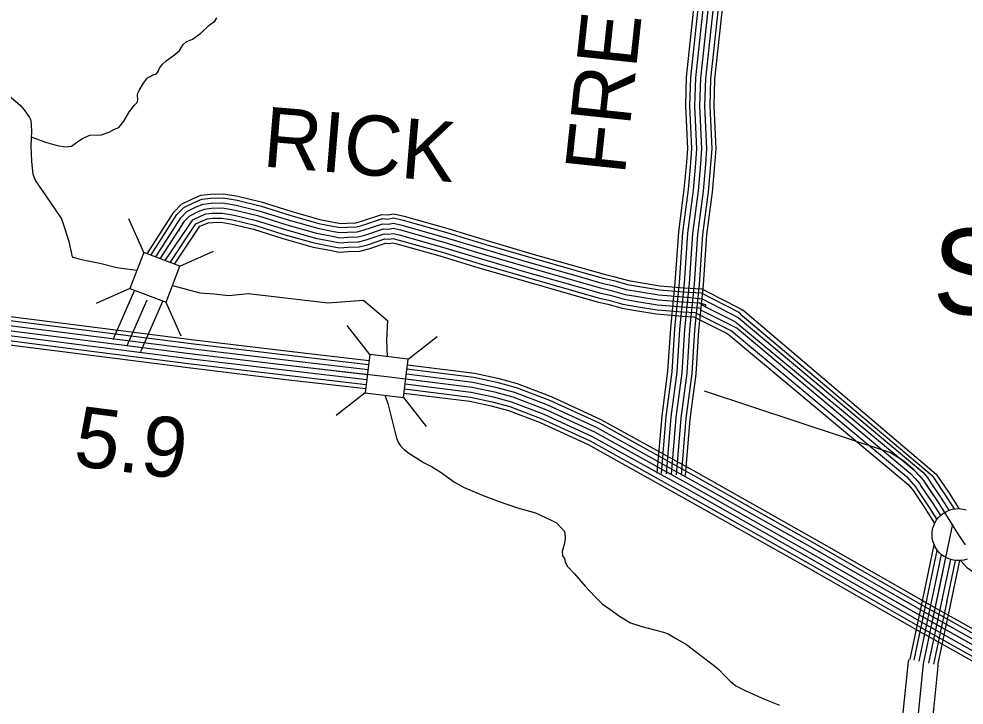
# Model space of a CAD drawing. Extents: x 1551132 to 1791609, y 378168 to 563823.
# Drawn here: x 1690071 to 1695891, y 434888 to 439114 of the extents above; entities that cross this region are included whole.
import ezdxf

# ---------------------------------------------------------------- set-up
doc = ezdxf.new("R2010")
doc.units = 0
for name, color, linetype in [('DESIGN - ROW - Right-of-Way and Easement Labels', 7, 'Continuous'), ('DESIGN - TRAFFIC CONTROL PERMANENT - Signalization', 7, 'Continuous'), ('DESIGN - TRANSPORTATION - Text', 7, 'Continuous'), ('SURVEY - CENTERLINE - Preliminary Text', 7, 'Continuous'), ('SURVEY - CONTOURS - Index with Text', 7, 'Continuous'), ('SURVEY - DRAINAGE - Storm Sewer', 7, 'Continuous'), ('SURVEY - PROPERTY - Owners', 7, 'Continuous'), ('SURVEY - TRANSPORTATION - Roads', 7, 'Continuous'), ('SURVEY - VEGETATION - Features with Text', 7, 'Continuous')]:
    doc.layers.add(name, color=color, linetype=linetype)

msp = doc.modelspace()

# ---------------------------------------------------------------- linework, layer by layer
at = {"layer": 'DESIGN - TRANSPORTATION - Text'}
for points in [[(1690147.225, 438387.515), (1690234.439, 438354.214), (1690306.237, 438335.339), (1690358.145, 438326.714), (1690394.185, 438330.297), (1690440.568, 438363.781), (1690462.725, 438377.532), (1690488.858, 438389.24), (1690506.941, 438397.032), (1690578.989, 438400.182), (1690627.163, 438415.633), (1690659.388, 438435.267), (1690685.495, 438444.975), (1690717.945, 438484.635), (1690752.61, 438544.286), (1690783.035, 438581.97), (1690799.234, 438599.796), (1690803.393, 438613.763), (1690801.743, 438645.822), (1690803.859, 438655.806), (1690812.059, 438673.731), (1690838.55, 438717.466), (1690862.925, 438751.217), (1690879.016, 438759.033), (1690895.124, 438768.85), (1690917.215, 438776.601), (1690927.365, 438790.493), (1690937.59, 438810.401), (1690955.881, 438836.21), (1690978.105, 438855.969), (1691028.521, 438893.412), (1691058.812, 438919.088), (1691083.236, 438956.839), (1691101.411, 438972.639), (1691139.61, 438990.206), (1691192.017, 439025.624), (1691242.566, 439075.084), (1691276.857, 439100.709), (1691289.081, 439120.585)], [(1689997.712, 438651.355), (1690078.951, 438582.32), (1690102.642, 438554.003), (1690122.35, 438527.744), (1690136.133, 438507.552), (1690143.933, 438489.443), (1690149.216, 438425.308), (1690144.15, 438329.255), (1690149.099, 438235.094), (1690156.233, 438156.917), (1690173.79, 438116.666), (1690215.139, 438058.106), (1690293.854, 437941.045), (1690333.203, 437882.51), (1690354.511, 437820.184), (1690377.669, 437743.823), (1690398.618, 437649.471), (1690439.376, 437636.221), (1690476.35, 437628.829), (1690569.314, 437608.745), (1690673.903, 437582.319), (1690798.026, 437566.919)], [(1691016.354, 437472.733), (1691185.2, 437426.949), (1691271.823, 437421.665), (1691362.679, 437410.04), (1691483.118, 437422.715), (1691747.22, 437391.015), (1691973.29, 437365.647), (1692193.026, 437382.556), (1692340.923, 437255.72), (1692334.464, 437134.617), (1692339.314, 437033.256)], [(1692323.889, 436795.349), (1692325.314, 436791.658), (1692342.797, 436745.39), (1692375.33, 436612.861), (1692396.438, 436532.518), (1692408.104, 436502.342), (1692419.904, 436484.183), (1692443.661, 436461.874), (1692471.419, 436439.523), (1692566.767, 436380.322), (1692610.524, 436357.78), (1692664.165, 436325.104), (1692753.454, 436259.977), (1692813.094, 436227.226), (1692928.558, 436177.809), (1693028.181, 436142.583), (1693141.753, 436103.19), (1693251.417, 436071.856), (1693348.932, 436026.646), (1693380.756, 436010.254), (1693408.439, 435981.895), (1693424.263, 435965.687)], [(1693424.263, 435965.687), (1693432.105, 435951.578), (1693433.663, 435911.518), (1693429.28, 435877.526), (1693416.797, 435833.625), (1693418.505, 435807.574), (1693430.321, 435791.415), (1693434.055, 435767.348), (1693447.771, 435741.156), (1693491.278, 435696.588), (1693558.435, 435619.703), (1693619.717, 435554.901), (1693665.207, 435508.308), (1693708.873, 435477.757), (1693768.405, 435435.006), (1693835.953, 435394.155), (1693905.71, 435371.305), (1693993.466, 435348.237), (1694039.357, 435337.679), (1694069.239, 435327.32), (1694120.905, 435296.669), (1694182.503, 435259.893), (1694269.768, 435192.783), (1694345.141, 435135.832), (1694382.807, 435105.348), (1694412.431, 435070.955), (1694452.005, 435032.446), (1694485.721, 435006.012), (1694543.403, 434977.294), (1694660.825, 434923.843), (1694754.423, 434886.692)]]:
    msp.add_lwpolyline(points, dxfattribs=at)
at = {"layer": 'SURVEY - CENTERLINE - Preliminary Text'}
for points in [[(1681622.025, 439012.586), (1682099.83, 438872.182), (1683124.214, 438579.092), (1684451.083, 438193.607), (1685427.977, 437892.65), (1685684.321, 437815.24), (1685789.718, 437786.239), (1686023.229, 437753.505), (1686441.986, 437702.812), (1687049.722, 437632.735), (1687947.351, 437524.691), (1688790.781, 437427.056), (1689660.927, 437327.162), (1690457.1, 437225.726), (1691150.425, 437137.108), (1691735.637, 437067.231), (1692227.308, 437010.672)], [(1681606.675, 438959.026), (1682084.314, 438818.672), (1683108.781, 438525.549), (1684435.117, 438140.231), (1685411.719, 437839.357), (1685668.871, 437761.697), (1685778.418, 437731.562), (1686016.013, 437698.253), (1686435.453, 437647.477), (1687043.197, 437577.392), (1687940.818, 437469.357), (1688784.398, 437371.704), (1689654.227, 437271.844), (1690450.05, 437170.458), (1691143.592, 437081.806), (1691729.153, 437011.896), (1692220.509, 436955.37)], [(1681615.192, 438988.835), (1682092.947, 438848.448), (1683117.364, 438555.341), (1684444, 438169.932), (1685420.768, 437869.008), (1685677.471, 437791.489), (1685784.71, 437761.98), (1686020.029, 437728.996), (1686439.086, 437678.27), (1687046.83, 437608.185), (1687944.451, 437500.149), (1688787.948, 437402.497), (1689657.952, 437302.62), (1690453.975, 437201.209), (1691147.4, 437112.574), (1691732.762, 437042.681), (1692224.275, 436986.138)], [(1681589.559, 438899.433), (1682067.048, 438759.121), (1683091.598, 438465.98), (1684417.334, 438080.829), (1685393.636, 437780.055), (1685651.688, 437702.128), (1685765.835, 437670.711), (1686007.98, 437636.768), (1686428.17, 437585.909), (1687035.947, 437515.824), (1687933.551, 437407.788), (1688777.298, 437310.103), (1689646.777, 437210.292), (1690442.2, 437108.957), (1691135.992, 437020.271), (1691721.937, 436950.311), (1692212.95, 436893.827)], [(1681598.117, 438929.225), (1682075.681, 438788.897), (1683100.19, 438495.764), (1684426.225, 438110.53), (1685402.677, 437809.706), (1685660.279, 437731.912), (1685772.127, 437701.137), (1686011.996, 437667.511), (1686431.811, 437616.693), (1687039.572, 437546.608), (1687937.184, 437438.572), (1688780.848, 437340.904), (1689650.502, 437241.068), (1690446.125, 437139.708), (1691139.792, 437051.039), (1691725.545, 436981.104), (1692216.717, 436924.594)], [(1681573.909, 438844.915), (1682051.256, 438704.644), (1683075.89, 438411.479), (1684401.076, 438026.494), (1685377.086, 437725.804), (1685635.963, 437647.627), (1685754.327, 437615.051), (1686000.638, 437580.525), (1686421.52, 437529.582), (1687029.306, 437459.489), (1687926.901, 437351.462), (1688770.806, 437253.76), (1689639.961, 437153.983), (1690435.026, 437052.697), (1691129.034, 436963.978), (1691715.337, 436893.985), (1692206.051, 436837.525)], [(1681581.017, 438869.624), (1682058.414, 438729.345), (1683083.015, 438436.188), (1684408.451, 438051.128), (1685384.586, 437750.404), (1685643.088, 437672.336), (1685759.544, 437640.293), (1686003.963, 437606.026), (1686424.536, 437555.116), (1687032.314, 437485.032), (1687929.918, 437376.996), (1688773.748, 437279.31), (1689643.052, 437179.517), (1690438.275, 437078.206), (1691132.184, 436989.504), (1691718.329, 436919.527), (1692209.192, 436863.059)], [(1689650.502, 437241.068), (1690446.125, 437139.708), (1691139.792, 437051.039), (1691725.545, 436981.104), (1692353.297, 436908.886), (1692861.069, 436845.468), (1692998.932, 436816.525), (1693112.779, 436785.733), (1693314.366, 436708.306), (1693615.601, 436570.136), (1694195.795, 436247.878), (1694941.444, 435828.392), (1695581.379, 435461.683), (1696362.927, 435023.938)], [(1692460.203, 436958.02), (1692871.293, 436906.678), (1693013.407, 436876.844), (1693132.037, 436844.751), (1693338.432, 436765.482), (1693643.617, 436625.496), (1694226.045, 436301.996), (1694972.052, 435882.31), (1695693.16, 435469.075)], [(1692463.211, 436982.546), (1692875.377, 436931.07), (1693019.173, 436900.886), (1693139.712, 436868.285), (1693348.024, 436788.275), (1693654.783, 436647.571), (1694238.103, 436323.571), (1694984.26, 435903.802), (1695624.12, 435537.135), (1695673.177, 435509.692)], [(1692456.428, 436927.253), (1692866.185, 436876.068), (1693006.165, 436846.684), (1693122.412, 436815.242), (1693326.399, 436736.89), (1693629.609, 436597.82), (1694210.92, 436274.937), (1694956.752, 435855.351), (1695672.969, 435444.932)], [(1692448.862, 436865.71), (1692855.952, 436814.867), (1692991.699, 436786.366), (1693103.146, 436756.224), (1693302.333, 436679.722), (1693601.593, 436542.452), (1694180.671, 436220.819), (1694926.136, 435801.433), (1695640.611, 435392.006)], [(1692452.653, 436896.477), (1692861.069, 436845.468), (1692998.932, 436816.525), (1693112.779, 436785.733), (1693314.366, 436708.306), (1693615.601, 436570.136), (1694195.795, 436247.878), (1694941.444, 435828.392), (1695646.211, 435424.532)], [(1692441.962, 436809.416), (1692846.602, 436758.874), (1692978.457, 436731.19), (1693085.53, 436702.231), (1693280.325, 436627.412), (1693575.96, 436491.809), (1694152.996, 436171.309), (1694898.137, 435752.107), (1695638.186, 435328.029)], [(1692445.095, 436834.934), (1692850.844, 436784.258), (1692984.457, 436756.207), (1693093.521, 436726.715), (1693290.3, 436651.129), (1693587.585, 436514.776), (1694165.546, 436193.759), (1694910.837, 435774.474), (1695650.194, 435350.796)], [(1695673.027, 435509.734), (1696405.543, 435099.465)], [(1695662.644, 435451.707), (1696378.16, 435050.939)], [(1695693.435, 435469.975), (1696393.402, 435077.931)], [(1695640.286, 435393.156), (1696347.694, 434996.938)], [(1695644.619, 435426.265), (1696362.927, 435023.938)], [(1695637.219, 435329.863), (1696319.82, 434947.545)], [(1695646.786, 435353.988), (1696332.453, 434969.945)]]:
    msp.add_lwpolyline(points, dxfattribs=at)
at = {"layer": 'SURVEY - CONTOURS - Index with Text'}
for points in [[(1694229.029, 439218.072), (1694179.68, 438754.902), (1694174.43, 438577.989), (1694186.705, 438315.357), (1694180.572, 438229.271), (1694165.755, 438065.559), (1694132.006, 437800.56), (1694110.015, 437491.01), (1694082.24, 437208.586), (1694064.682, 436943.671), (1694029.066, 436668.33), (1693999.083, 436316.038)], [(1694254.554, 439214.905), (1694205.355, 438753.152), (1694200.163, 438578.205), (1694212.471, 438315.04), (1694206.204, 438227.196), (1694191.321, 438062.767), (1694157.605, 437798.018), (1694135.639, 437488.843), (1694107.873, 437206.478), (1694090.29, 436941.171), (1694054.649, 436665.588), (1694024.708, 436313.854)], [(1694285.328, 439211.089), (1694236.304, 438751.051), (1694231.179, 438578.472), (1694243.52, 438314.665), (1694237.104, 438224.696), (1694222.146, 438059.417), (1694188.471, 437794.96), (1694166.53, 437486.227), (1694138.772, 437203.936), (1694121.156, 436938.154), (1694085.473, 436662.288), (1694055.59, 436311.229)], [(1694316.094, 439207.272), (1694267.253, 438748.943), (1694262.203, 438578.739), (1694274.569, 438314.282), (1694268.003, 438222.196), (1694252.97, 438056.058), (1694219.329, 437791.901), (1694197.421, 437483.61), (1694169.671, 437201.394), (1694152.022, 436935.137), (1694116.306, 436658.98), (1694086.481, 436308.596)], [(1694316.094, 439207.272), (1694267.253, 438748.943), (1694262.203, 438578.739), (1694274.569, 438314.282), (1694268.003, 438222.196), (1694252.97, 438056.058), (1694219.329, 437791.901), (1694197.421, 437483.61), (1694169.671, 437201.394), (1694152.022, 436935.137), (1694116.306, 436658.98), (1694086.481, 436308.596)], [(1694346.86, 439203.455), (1694298.202, 438746.835), (1694293.227, 438579.005), (1694305.619, 438313.898), (1694298.902, 438219.696), (1694283.794, 438052.7), (1694250.186, 437788.843), (1694228.312, 437480.993), (1694200.571, 437198.852), (1694182.888, 436932.121), (1694147.138, 436655.672), (1694117.372, 436305.962)], [(1694377.634, 439199.638), (1694329.152, 438744.735), (1694324.243, 438579.272), (1694336.668, 438313.523), (1694329.801, 438217.196), (1694314.618, 438049.35), (1694281.052, 437785.785), (1694259.203, 437478.377), (1694231.47, 437196.311), (1694213.754, 436929.104), (1694177.963, 436652.372), (1694148.255, 436303.337)], [(1694402.158, 439196.597), (1694353.834, 438743.051), (1694348.976, 438579.48), (1694361.426, 438313.223), (1694354.442, 438215.204), (1694339.193, 438046.666), (1694305.652, 437783.343), (1694283.835, 437476.293), (1694256.103, 437194.277), (1694238.37, 436926.695), (1694202.545, 436649.738), (1694172.888, 436301.237)]]:
    msp.add_lwpolyline(points, dxfattribs=at)
at = {"layer": 'SURVEY - DRAINAGE - Storm Sewer'}
for p, q in [((1690839.944, 437676.125), (1690747.539, 437883.606)), ((1691061.747, 437590.98), (1691269.236, 437683.369)), ((1690754.783, 437454.297), (1690547.293, 437361.908)), ((1690976.569, 437369.177), (1691068.949, 437161.696)), ((1692231.677, 437046.467), (1692091.848, 437225.439)), ((1692467.504, 437017.523), (1692646.484, 437157.361)), ((1692202.741, 436810.641), (1692023.761, 436670.803)), ((1692438.526, 436781.696), (1692578.356, 436602.716))]:
    msp.add_line(p, q, dxfattribs=at)
for points in [[(1690754.783, 437454.297), (1690976.61, 437369.177), (1691061.747, 437590.98), (1690839.944, 437676.125)], [(1692202.741, 436810.641), (1692438.568, 436781.696), (1692467.504, 437017.523), (1692231.677, 437046.467)]]:
    msp.add_lwpolyline(points, close=True, dxfattribs=at)
at = {"layer": 'SURVEY - PROPERTY - Owners'}
for points in [[(1690651.72, 437140.124), (1690784.701, 437444.641)], [(1690738.127, 437102.382), (1690861.141, 437384.056)], [(1690821.25, 437066.072), (1690956.813, 437376.481)], [(1695496.731, 434648.42), (1695499.989, 434681.529), (1695524.397, 434920.593), (1695548.471, 435156.441), (1695551.596, 435171.342)], [(1695445.79, 433943.084), (1695473.473, 433967.135), (1695491.356, 433987.011), (1695508.338, 434018.561), (1695518.53, 434042.479), (1695530.938, 434092.388), (1695552.263, 434250.276), (1695593.812, 434672.12), (1695641.769, 435141.924), (1695643.877, 435151.966)], [(1695680.718, 434629.078), (1695684.068, 434663.07), (1695708.434, 434901.81), (1695731.517, 435127.957), (1695732.65, 435133.324)]]:
    msp.add_lwpolyline(points, dxfattribs=at)
at = {"layer": 'SURVEY - TRANSPORTATION - Roads'}
for points in [[(1690860.332, 437668.047), (1691024.362, 437924.062), (1691071.319, 437973.063), (1691140.126, 438006.489), (1691191.558, 438027.439), (1691251.548, 438034.906), (1691330.113, 438036.348), (1691419.045, 438021.556), (1691562.408, 437986.472), (1691745.354, 437929.745), (1691924.333, 437878.753), (1692018.164, 437860.344), (1692052.713, 437853.894), (1692091.845, 437856.685), (1692145.344, 437857.777), (1692174.877, 437865.844), (1692305.74, 437909.27), (1692341.723, 437906.437), (1692378.68, 437913.379), (1692442.237, 437898.12), (1692711.856, 437822.143), (1692953.525, 437749.025), (1693230.01, 437667.798), (1693514.779, 437586.387), (1693673.891, 437541.07), (1693740.032, 437526.203), (1693823.413, 437501.835), (1693895.695, 437489.81), (1694018.275, 437470.785), (1694167.738, 437457.318), (1694275.502, 437451.709), (1694386.6, 437394.233), (1694511.997, 437331.073), (1694529.271, 437320.831)], [(1690884.832, 437660.346), (1691043.87, 437908.703), (1691086.102, 437952.762), (1691150.201, 437983.897), (1691197.85, 438003.314), (1691253.307, 438010.222), (1691328.297, 438011.589), (1691414.078, 437997.322), (1691555.808, 437962.638), (1691738.304, 437906.053), (1691918.558, 437854.702), (1692013.522, 437836.06), (1692051.305, 437829.01), (1692092.979, 437831.993), (1692148.902, 437833.126), (1692182.035, 437842.168), (1692308.782, 437884.236), (1692343.056, 437881.544), (1692378.047, 437888.111), (1692436.004, 437874.203), (1692704.923, 437798.417), (1692946.467, 437725.341), (1693223.127, 437644.055), (1693507.995, 437562.612), (1693667.792, 437517.111), (1693733.848, 437502.26), (1693817.896, 437477.693), (1693891.77, 437465.409), (1694015.267, 437446.242), (1694165.98, 437432.659), (1694271.527, 437427.167), (1694500.122, 437309.381), (1694516.663, 437299.572)], [(1690913.165, 437648.021), (1691068.344, 437889.436), (1691104.635, 437927.303), (1691162.834, 437955.571), (1691205.75, 437973.063), (1691255.515, 437979.255), (1691326.013, 437980.547), (1691407.836, 437966.938), (1691547.525, 437932.754), (1691729.471, 437876.336), (1691911.308, 437824.526), (1692007.689, 437805.617), (1692049.538, 437797.809), (1692094.404, 437801.009), (1692153.369, 437802.209), (1692191.001, 437812.484), (1692312.599, 437852.844), (1692344.723, 437850.31), (1692377.255, 437856.419), (1692428.179, 437844.194), (1692696.231, 437768.658), (1692937.609, 437695.632), (1693214.502, 437614.28), (1693499.496, 437532.803), (1693660.142, 437487.051), (1693726.099, 437472.234), (1693810.98, 437447.417), (1693886.845, 437434.8), (1694011.5, 437415.45), (1694163.788, 437401.724), (1694277.327, 437390.508), (1694500.647, 437274.13)], [(1690940.122, 437636.746), (1691092.819, 437870.169), (1691123.176, 437901.844), (1691175.467, 437927.245), (1691213.649, 437942.804), (1691257.715, 437948.287), (1691323.738, 437949.496), (1691401.603, 437936.545), (1691539.242, 437902.861), (1691720.629, 437846.618), (1691904.066, 437794.359), (1692001.864, 437775.167), (1692047.771, 437766.6), (1692095.82, 437770.033), (1692157.835, 437771.292), (1692199.976, 437782.8), (1692316.415, 437821.443), (1692346.398, 437819.085), (1692376.464, 437824.726), (1692420.354, 437814.193), (1692687.54, 437738.899), (1692928.751, 437665.922), (1693205.869, 437584.504), (1693490.987, 437502.993), (1693652.492, 437457.001), (1693718.34, 437442.2), (1693804.063, 437417.141), (1693881.928, 437404.191), (1694007.725, 437384.666), (1694161.588, 437370.799), (1694261.544, 437365.599), (1694299.277, 437341.115), (1694470.331, 437254.962), (1694484.839, 437246.362)], [(1691055.52, 437806.842), (1691062.278, 437822.484), (1691092.819, 437870.169), (1691123.176, 437901.844), (1691175.467, 437927.245), (1691213.649, 437942.804), (1691257.715, 437948.287), (1691323.738, 437949.496), (1691401.603, 437936.545), (1691539.242, 437902.861), (1691720.629, 437846.618), (1691904.066, 437794.359), (1692001.864, 437775.167), (1692047.771, 437766.6), (1692095.82, 437770.033), (1692157.835, 437771.292), (1692199.976, 437782.8), (1692316.415, 437821.443), (1692346.398, 437819.085), (1692376.464, 437824.726), (1692420.354, 437814.193), (1692687.54, 437738.899), (1692928.751, 437665.922), (1693205.869, 437584.504), (1693490.987, 437502.993), (1693652.492, 437457.001), (1693718.34, 437442.2), (1693804.063, 437417.141), (1693881.928, 437404.191), (1694007.725, 437384.666), (1694161.588, 437370.799), (1694261.544, 437365.599), (1694299.435, 437355.132), (1694299.277, 437341.115), (1694470.331, 437254.962), (1694485.047, 437246.237)], [(1690971.022, 437625.812), (1691141.718, 437876.385), (1691188.1, 437898.919), (1691221.549, 437912.545), (1691259.915, 437917.32), (1691321.463, 437918.445), (1691395.37, 437906.153), (1691530.959, 437872.969), (1691711.788, 437816.901), (1691896.825, 437764.191), (1691996.039, 437744.716), (1692046.005, 437735.391), (1692097.237, 437739.057), (1692162.302, 437740.374), (1692208.951, 437753.116), (1692320.232, 437790.042), (1692348.073, 437787.859), (1692375.672, 437793.034), (1692412.529, 437784.192), (1692678.848, 437709.14), (1692919.893, 437636.213), (1693197.236, 437554.728), (1693482.479, 437473.184), (1693644.842, 437426.95), (1693710.582, 437412.166), (1693797.147, 437386.866), (1693877.012, 437373.582), (1694003.95, 437353.881), (1694159.388, 437339.873), (1694256.553, 437334.814), (1694268.169, 437331.606), (1694268.061, 437322.122), (1694493.205, 437208.736)], [(1691002.171, 437613.845), (1691160.251, 437850.926), (1691200.733, 437870.594), (1691229.449, 437882.294), (1691262.123, 437886.352), (1691319.18, 437887.403), (1691389.129, 437875.769), (1691522.675, 437843.085), (1691702.954, 437787.183), (1691889.575, 437734.015), (1691990.206, 437714.273), (1692044.238, 437704.19), (1692098.662, 437708.073), (1692166.769, 437709.457), (1692217.917, 437723.432), (1692324.048, 437758.65), (1692349.739, 437756.625), (1692374.88, 437761.341), (1692404.705, 437754.183), (1692670.157, 437679.381), (1692911.034, 437606.504), (1693188.611, 437524.952), (1693473.979, 437443.375), (1693637.192, 437396.891), (1693702.832, 437382.14), (1693790.23, 437356.59), (1693872.087, 437342.973), (1694000.184, 437323.089), (1694157.197, 437308.939), (1694236.861, 437304.797), (1694236.845, 437303.139), (1694457.59, 437191.961)], [(1691028.162, 437603.87), (1691185.208, 437837.568), (1691211.216, 437847.093), (1691235.999, 437857.193), (1691263.948, 437860.668), (1691317.289, 437861.643), (1691383.962, 437850.56), (1691515.809, 437818.292), (1691695.621, 437762.533), (1691883.567, 437708.99), (1691985.373, 437689.014), (1692042.771, 437678.297), (1692099.837, 437682.381), (1692170.468, 437683.814), (1692225.359, 437698.798), (1692327.215, 437732.607), (1692351.131, 437730.724), (1692374.222, 437735.057), (1692398.213, 437729.299), (1692662.94, 437654.697), (1692903.685, 437581.862), (1693181.453, 437500.252), (1693466.921, 437418.641), (1693630.842, 437371.957), (1693696.399, 437357.223), (1693784.497, 437331.472), (1693868.003, 437317.58), (1693997.05, 437297.555), (1694155.372, 437283.288), (1694226.428, 437279.588), (1694428.19, 437177.969), (1694440.315, 437170.785)], [(1694528.763, 437321.814), (1695718.285, 436309.255), (1695798.108, 436193.185), (1695857.415, 436098.474)], [(1694500.647, 437274.13), (1695635.737, 436323.189), (1695664.678, 436289.304), (1695678.761, 436268.462)], [(1694511.863, 437298.555), (1695694.102, 436301.138)], [(1694457.59, 437191.961), (1695535.289, 436296.429), (1695565.521, 436262.204), (1695590.563, 436232.886), (1695601.712, 436216.377)], [(1694484.839, 437246.362), (1695581.646, 436337.606), (1695612.329, 436302.863), (1695639.97, 436270.496), (1695653.078, 436251.103)], [(1694493.205, 437208.736), (1695563.597, 436311.213), (1695588.921, 436282.537), (1695615.262, 436251.687), (1695627.395, 436233.745)], [(1694437.915, 437171.727), (1695546.855, 436245.995), (1695570.863, 436217.886), (1695581.238, 436202.535)], [(1694290.668, 436823.451), (1695437.641, 436443.292), (1695519.314, 436392.082), (1695574.796, 436345.364), (1695612.329, 436302.863), (1695639.97, 436270.496), (1695724.576, 436145.334), (1695848.373, 435947.621), (1695897.564, 435874.944)], [(1695678.752, 436268.479), (1695750.559, 436162.243), (1695797.316, 436087.574)], [(1695694.102, 436301.138), (1695776.55, 436179.16), (1695828.64, 436095.966)], [(1695581.229, 436202.552), (1695651.886, 436098.024), (1695708.801, 436007.13)], [(1695601.704, 436216.394), (1695672.602, 436111.508), (1695723.109, 436030.839)], [(1695627.387, 436233.761), (1695698.593, 436128.425), (1695744.959, 436054.373)], [(1695653.069, 436251.12), (1695724.576, 436145.334), (1695769.75, 436073.182)], [(1695643.877, 435151.966), (1695822.115, 436001.347)], [(1695636.361, 435538.376), (1695707.093, 435875.46)], [(1695663.427, 435547.01), (1695724.934, 435840.101)], [(1695695.801, 435550.352), (1695751.184, 435814.275)], [(1695726.684, 435546.568), (1695779.316, 435797.375)], [(1695756.2, 435536.276), (1695808.241, 435784.275)], [(1695784.974, 435522.484), (1695838.582, 435777.949)], [(1695807.349, 435503.842), (1695864.714, 435777.233)], [(1695868.564, 435778.474), (1695908.213, 435735.465), (1696123.958, 435593.461), (1696205.556, 435547.06), (1696271.78, 435517.384), (1696326.187, 435497.376)], [(1695559.013, 435169.775), (1695636.303, 435538.11)], [(1695583.204, 435164.7), (1695662.969, 435544.777)], [(1695613.537, 435158.333), (1695696.301, 435552.71)], [(1695643.877, 435151.966), (1695727.642, 435551.093)], [(1695674.218, 435145.599), (1695758.075, 435545.127)], [(1695704.551, 435139.233), (1695785.683, 435525.934)], [(1695729.725, 435133.949), (1695807.382, 435504.009)]]:
    msp.add_lwpolyline(points, dxfattribs=at)
at = {"layer": 'SURVEY - VEGETATION - Features with Text'}
msp.add_lwpolyline([(1695909.013, 435786.25), (1695889.339, 435780.874), (1695868.114, 435777.324), (1695835.515, 435778.116), (1695807.116, 435784.55), (1695782.125, 435795.025), (1695758.642, 435808.725), (1695739.217, 435825.084), (1695724.193, 435841.493), (1695711.743, 435862.31), (1695700.926, 435892.902), (1695694.702, 435914.495), (1695694.885, 435947.804), (1695696.935, 435974.171), (1695707.943, 436005.089), (1695719.801, 436026.364), (1695733.576, 436043.94), (1695744.851, 436054.398), (1695759.325, 436066.949), (1695775.866, 436076.782), (1695794.333, 436085.924), (1695817.799, 436094.049), (1695840.115, 436097.091), (1695858.048, 436098.099), (1695885.056, 436095.341), (1695903.672, 436090.391)], dxfattribs=at)

# ---------------------------------------------------------------- texts
at = {"layer": 'DESIGN - ROW - Right-of-Way and Easement Labels'}
for s, height, rotation, p in [('FRED', 370.0095, 83.9182944, (1693801.005, 438147.727)), ('RICK', 369.9914, 355.2655361, (1691565.433, 438205.861))]:
    msp.add_text(s, height=height, rotation=rotation, dxfattribs=at).set_placement(p)
at = {"layer": 'DESIGN - TRAFFIC CONTROL PERMANENT - Signalization'}
msp.add_text('5.9', height=369.9916, rotation=352.7151, dxfattribs=at).set_placement((1690399.274, 436364.672))
at = {"layer": 'SURVEY - VEGETATION - Features with Text'}
msp.add_text('Station', height=527.9876, rotation=0.0000278, dxfattribs=at).set_placement((1695696.269, 437293.539))

doc.saveas('drawing.dxf')
